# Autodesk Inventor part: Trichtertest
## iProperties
Author: Bonse
Created: 2003-09
Part Number: Trichtertest
Material: 1.0037
Document SubType Name: Blech
Designer: Bonse
Control State: 0
Master: False
Checked Out: False
PropertySet Name: Design Tracking Control
Shininess: 20.0
Angle Display Precision: 2
Document Length Units: 11269
Document Angle Units: 11283
Document Time Units: 11279
Document Mass Units: 11290
Document Length Units Precision: 3
Document Angle Units Precision: 2
Compacted: False
PropertySet Name: _Private Model Information
Density: 0.0
Volumn: 0.0
Area: 0.0
PropertySet Name: Model Information
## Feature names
1. Drehung1 [Revolution]
